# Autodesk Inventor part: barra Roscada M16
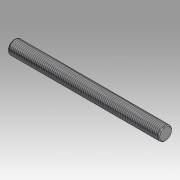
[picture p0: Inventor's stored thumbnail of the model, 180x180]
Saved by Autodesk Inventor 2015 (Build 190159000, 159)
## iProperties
Created: 2014-10
Part Number: barra Roscada M16
Material: Generic
Document SubType Name: Modeling
Designer: IvoBoss
Mass: 36.143 g
Surface Area: 93.8842 cm^2
Volume: 36.143 cm^3
Density: 1 g/cm^3
Appearance: Chrome - Polished
Description: BARRA ROSCADA
Author: IvoBoss
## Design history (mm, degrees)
sketch "Sketch1"
  geometry: C1 r 8 at (0, 0); 1 further point
  constraints: 1 centre point, 1 coincident
  dimensions: "d0" = 16 diameter of C1
extrude "Extrusion1" new body sketch "Sketch1" stored distance "d1" = 180; taper "d2" = 0 deg
chamfer "Chamfer1" distance "d3" = 1; stored, may be unused: second distance "d4" = 2, angle "d5" = 45 deg
thread "Thread1" dims "d6" = 10, "d7" = 0
body "Solid1"
